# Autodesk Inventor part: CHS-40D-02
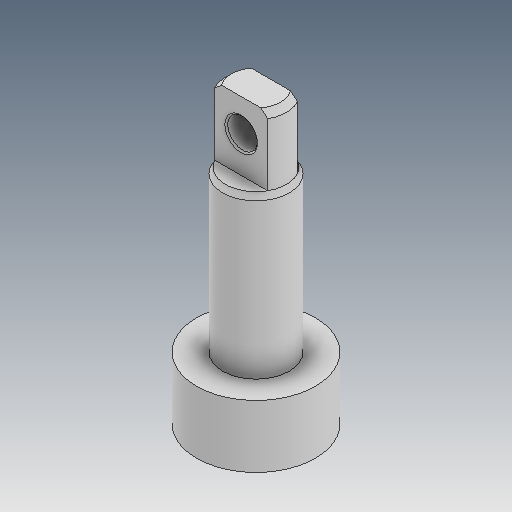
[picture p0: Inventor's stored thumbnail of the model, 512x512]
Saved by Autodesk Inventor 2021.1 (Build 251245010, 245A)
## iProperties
Created: 2019-04
Part Number: CHS-40D-02
Material: Ogólny
Document SubType Name: Modeling
Designer: user
Density: 1 g/cm^3
Appearance: Domyślna
Author: user
Revision Number: ÈÎºÎ
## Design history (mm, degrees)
feature "ÊäÈë1"
feature "ÊäÈë2"
node "Bryła1"
node "Bryła2"
